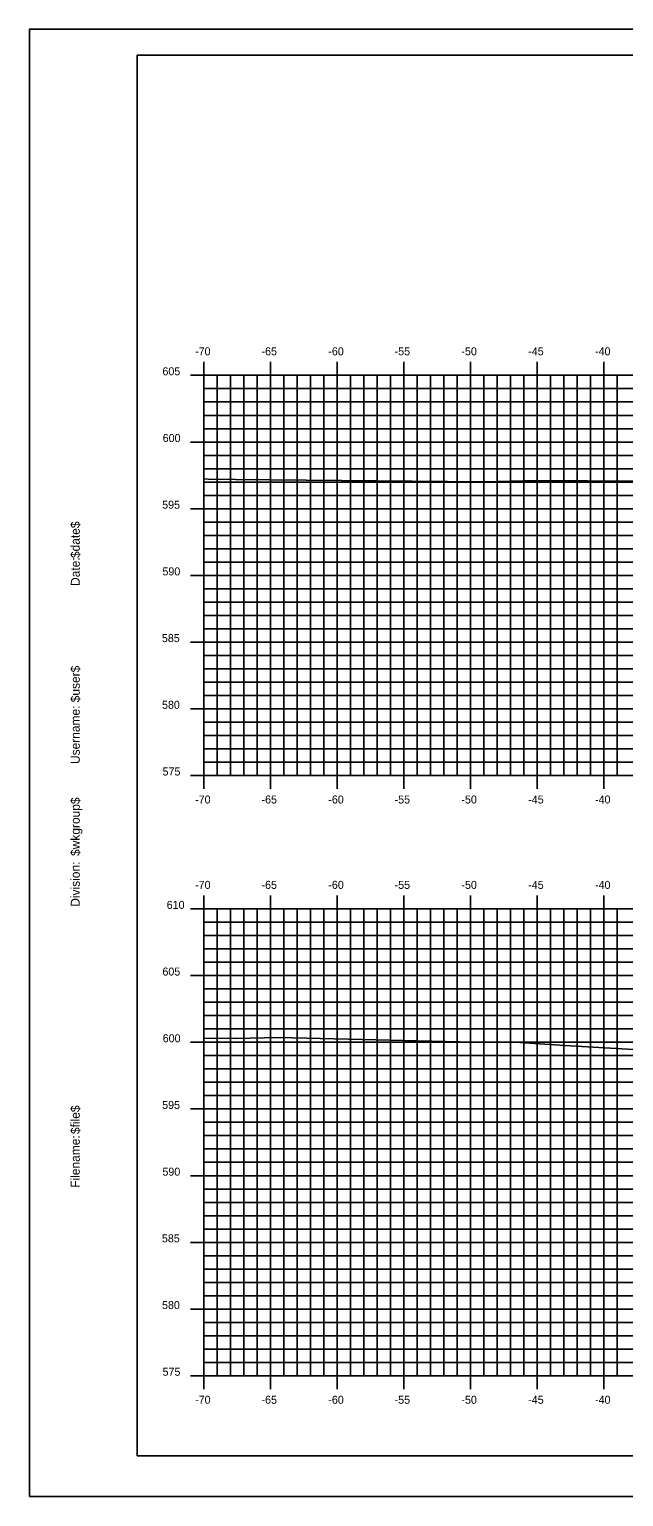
# Model space of a CAD drawing. Extents: x 1073864 to 1074034, y 779716 to 779826.
# Drawn here: x 1073864.4 to 1073908.9, y 779715.6 to 779825.6 of the extents above; entities that cross this region are included whole.
import ezdxf

# ---------------------------------------------------------------- set-up
doc = ezdxf.new("R2010")
doc.units = 0
for name, color, linetype in [('BORDER', 7, 'Continuous'), ('H_V ANNOTATION', 7, 'Continuous'), ('MAJOR', 7, 'Continuous'), ('MINOR', 7, 'Continuous'), ('PLOT BOUNDARY', 7, 'Continuous'), ('S_Roadway_Centerline', 7, 'Continuous')]:
    doc.layers.add(name, color=color, linetype=linetype)

msp = doc.modelspace()

# ---------------------------------------------------------------- linework, layer by layer
at = {"layer": 'BORDER'}
msp.add_lwpolyline([(1073872.47, 779718.71), (1074032.47, 779718.71), (1074032.47, 779823.71), (1073872.47, 779823.71)], close=True, dxfattribs=at)
at = {"layer": 'MAJOR'}
for p, q in [((1073877.47, 779800.71), (1073877.47, 779799.71)), ((1073882.47, 779800.71), (1073882.47, 779799.71)), ((1073887.47, 779800.71), (1073887.47, 779799.71)), ((1073892.47, 779800.71), (1073892.47, 779799.71)), ((1073897.47, 779800.71), (1073897.47, 779799.71)), ((1073902.47, 779800.71), (1073902.47, 779799.71)), ((1073907.47, 779800.71), (1073907.47, 779799.71)), ((1073876.47, 779799.71), (1073877.47, 779799.71)), ((1073877.47, 779799.71), (1074017.47, 779799.71)), ((1073877.47, 779769.71), (1073877.47, 779799.71)), ((1073877.47, 779769.71), (1073877.47, 779799.71)), ((1073877.47, 779799.71), (1074017.47, 779799.71)), ((1073882.47, 779769.71), (1073882.47, 779799.71)), ((1073887.47, 779769.71), (1073887.47, 779799.71)), ((1073892.47, 779769.71), (1073892.47, 779799.71)), ((1073897.47, 779769.71), (1073897.47, 779799.71)), ((1073902.47, 779769.71), (1073902.47, 779799.71)), ((1073907.47, 779769.71), (1073907.47, 779799.71)), ((1073876.47, 779794.71), (1073877.47, 779794.71)), ((1073877.47, 779794.71), (1074017.47, 779794.71)), ((1073876.47, 779789.71), (1073877.47, 779789.71)), ((1073877.47, 779789.71), (1074017.47, 779789.71)), ((1073876.47, 779784.71), (1073877.47, 779784.71)), ((1073877.47, 779784.71), (1074017.47, 779784.71)), ((1073876.47, 779779.71), (1073877.47, 779779.71)), ((1073877.47, 779779.71), (1074017.47, 779779.71)), ((1073876.47, 779774.71), (1073877.47, 779774.71)), ((1073877.47, 779774.71), (1074017.47, 779774.71)), ((1073876.47, 779769.71), (1073877.47, 779769.71)), ((1073877.47, 779769.71), (1074017.47, 779769.71)), ((1073877.47, 779769.71), (1074017.47, 779769.71)), ((1073877.47, 779768.7), (1073877.47, 779769.71)), ((1073882.47, 779768.7), (1073882.47, 779769.71)), ((1073887.47, 779768.7), (1073887.47, 779769.71)), ((1073892.47, 779768.7), (1073892.47, 779769.71)), ((1073897.47, 779768.7), (1073897.47, 779769.71)), ((1073902.47, 779768.7), (1073902.47, 779769.71)), ((1073907.47, 779768.7), (1073907.47, 779769.71)), ((1073877.47, 779760.71), (1073877.47, 779759.71)), ((1073882.47, 779760.71), (1073882.47, 779759.71)), ((1073887.47, 779760.71), (1073887.47, 779759.71)), ((1073892.47, 779760.71), (1073892.47, 779759.71)), ((1073897.47, 779760.71), (1073897.47, 779759.71)), ((1073902.47, 779760.71), (1073902.47, 779759.71)), ((1073907.47, 779760.71), (1073907.47, 779759.71)), ((1073876.47, 779759.71), (1073877.47, 779759.71)), ((1073877.47, 779759.71), (1074017.47, 779759.71)), ((1073877.47, 779724.71), (1073877.47, 779759.71)), ((1073877.47, 779724.71), (1073877.47, 779759.71)), ((1073877.47, 779759.71), (1074017.47, 779759.71)), ((1073882.47, 779724.71), (1073882.47, 779759.71)), ((1073887.47, 779724.71), (1073887.47, 779759.71)), ((1073892.47, 779724.71), (1073892.47, 779759.71)), ((1073897.47, 779724.71), (1073897.47, 779759.71)), ((1073902.47, 779724.71), (1073902.47, 779759.71)), ((1073907.47, 779724.71), (1073907.47, 779759.71)), ((1073876.47, 779754.71), (1073877.47, 779754.71)), ((1073877.47, 779754.71), (1074017.47, 779754.71)), ((1073876.47, 779749.71), (1073877.47, 779749.71)), ((1073877.47, 779749.71), (1074017.47, 779749.71)), ((1073876.47, 779744.71), (1073877.47, 779744.71)), ((1073877.47, 779744.71), (1074017.47, 779744.71)), ((1073876.47, 779739.71), (1073877.47, 779739.71)), ((1073877.47, 779739.71), (1074017.47, 779739.71)), ((1073876.47, 779734.71), (1073877.47, 779734.71)), ((1073877.47, 779734.71), (1074017.47, 779734.71)), ((1073876.47, 779729.71), (1073877.47, 779729.71)), ((1073877.47, 779729.71), (1074017.47, 779729.71)), ((1073876.47, 779724.71), (1073877.47, 779724.71)), ((1073877.47, 779724.71), (1074017.47, 779724.71)), ((1073877.47, 779724.71), (1074017.47, 779724.71)), ((1073877.47, 779723.7), (1073877.47, 779724.71)), ((1073882.47, 779723.7), (1073882.47, 779724.71)), ((1073887.47, 779723.7), (1073887.47, 779724.71)), ((1073892.47, 779723.7), (1073892.47, 779724.71)), ((1073897.47, 779723.7), (1073897.47, 779724.71)), ((1073902.47, 779723.7), (1073902.47, 779724.71)), ((1073907.47, 779723.7), (1073907.47, 779724.71))]:
    msp.add_line(p, q, dxfattribs=at)
at = {"layer": 'MINOR'}
for p, q in [((1073878.47, 779769.71), (1073878.47, 779799.71)), ((1073879.47, 779769.71), (1073879.47, 779799.71)), ((1073880.47, 779769.71), (1073880.47, 779799.71)), ((1073881.47, 779769.71), (1073881.47, 779799.71)), ((1073883.47, 779769.71), (1073883.47, 779799.71)), ((1073884.47, 779769.71), (1073884.47, 779799.71)), ((1073885.47, 779769.71), (1073885.47, 779799.71)), ((1073886.47, 779769.71), (1073886.47, 779799.71)), ((1073888.47, 779769.71), (1073888.47, 779799.71)), ((1073889.47, 779769.71), (1073889.47, 779799.71)), ((1073890.47, 779769.71), (1073890.47, 779799.71)), ((1073891.47, 779769.71), (1073891.47, 779799.71)), ((1073893.47, 779769.71), (1073893.47, 779799.71)), ((1073894.47, 779769.71), (1073894.47, 779799.71)), ((1073895.47, 779769.71), (1073895.47, 779799.71)), ((1073896.47, 779769.71), (1073896.47, 779799.71)), ((1073898.47, 779769.71), (1073898.47, 779799.71)), ((1073899.47, 779769.71), (1073899.47, 779799.71)), ((1073900.47, 779769.71), (1073900.47, 779799.71)), ((1073901.47, 779769.71), (1073901.47, 779799.71)), ((1073903.47, 779769.71), (1073903.47, 779799.71)), ((1073904.47, 779769.71), (1073904.47, 779799.71)), ((1073905.47, 779769.71), (1073905.47, 779799.71)), ((1073906.47, 779769.71), (1073906.47, 779799.71)), ((1073908.47, 779769.71), (1073908.47, 779799.71)), ((1073877.47, 779798.71), (1074017.47, 779798.71)), ((1073877.47, 779798.71), (1073878.47, 779798.71)), ((1073877.47, 779797.71), (1074017.47, 779797.71)), ((1073877.47, 779797.71), (1073878.47, 779797.71)), ((1073877.47, 779796.71), (1074017.47, 779796.71)), ((1073877.47, 779796.71), (1073878.47, 779796.71)), ((1073877.47, 779795.71), (1074017.47, 779795.71)), ((1073877.47, 779795.71), (1073878.47, 779795.71)), ((1073877.47, 779793.71), (1074017.47, 779793.71)), ((1073877.47, 779793.71), (1073878.47, 779793.71)), ((1073877.47, 779792.71), (1074017.47, 779792.71)), ((1073877.47, 779792.71), (1073878.47, 779792.71)), ((1073877.47, 779791.71), (1074017.47, 779791.71)), ((1073877.47, 779791.71), (1073878.47, 779791.71)), ((1073877.47, 779790.71), (1074017.47, 779790.71)), ((1073877.47, 779790.71), (1073878.47, 779790.71)), ((1073877.47, 779788.71), (1074017.47, 779788.71)), ((1073877.47, 779788.71), (1073878.47, 779788.71)), ((1073877.47, 779787.71), (1074017.47, 779787.71)), ((1073877.47, 779787.71), (1073878.47, 779787.71)), ((1073877.47, 779786.71), (1074017.47, 779786.71)), ((1073877.47, 779786.71), (1073878.47, 779786.71)), ((1073877.47, 779785.71), (1074017.47, 779785.71)), ((1073877.47, 779785.71), (1073878.47, 779785.71)), ((1073877.47, 779783.71), (1074017.47, 779783.71)), ((1073877.47, 779783.71), (1073878.47, 779783.71)), ((1073877.47, 779782.71), (1074017.47, 779782.71)), ((1073877.47, 779782.71), (1073878.47, 779782.71)), ((1073877.47, 779781.71), (1074017.47, 779781.71)), ((1073877.47, 779781.71), (1073878.47, 779781.71)), ((1073877.47, 779780.71), (1074017.47, 779780.71)), ((1073877.47, 779780.71), (1073878.47, 779780.71)), ((1073877.47, 779778.71), (1074017.47, 779778.71)), ((1073877.47, 779778.71), (1073878.47, 779778.71)), ((1073877.47, 779777.71), (1074017.47, 779777.71)), ((1073877.47, 779777.71), (1073878.47, 779777.71)), ((1073877.47, 779776.71), (1074017.47, 779776.71)), ((1073877.47, 779776.71), (1073878.47, 779776.71)), ((1073877.47, 779775.71), (1074017.47, 779775.71)), ((1073877.47, 779775.71), (1073878.47, 779775.71)), ((1073877.47, 779773.71), (1074017.47, 779773.71)), ((1073877.47, 779773.71), (1073878.47, 779773.71)), ((1073877.47, 779772.71), (1074017.47, 779772.71)), ((1073877.47, 779772.71), (1073878.47, 779772.71)), ((1073877.47, 779771.71), (1074017.47, 779771.71)), ((1073877.47, 779771.71), (1073878.47, 779771.71)), ((1073877.47, 779770.71), (1074017.47, 779770.71)), ((1073877.47, 779770.71), (1073878.47, 779770.71)), ((1073878.47, 779724.71), (1073878.47, 779759.71)), ((1073879.47, 779724.71), (1073879.47, 779759.71)), ((1073880.47, 779724.71), (1073880.47, 779759.71)), ((1073881.47, 779724.71), (1073881.47, 779759.71)), ((1073883.47, 779724.71), (1073883.47, 779759.71)), ((1073884.47, 779724.71), (1073884.47, 779759.71)), ((1073885.47, 779724.71), (1073885.47, 779759.71)), ((1073886.47, 779724.71), (1073886.47, 779759.71)), ((1073888.47, 779724.71), (1073888.47, 779759.71)), ((1073889.47, 779724.71), (1073889.47, 779759.71)), ((1073890.47, 779724.71), (1073890.47, 779759.71)), ((1073891.47, 779724.71), (1073891.47, 779759.71)), ((1073893.47, 779724.71), (1073893.47, 779759.71)), ((1073894.47, 779724.71), (1073894.47, 779759.71)), ((1073895.47, 779724.71), (1073895.47, 779759.71)), ((1073896.47, 779724.71), (1073896.47, 779759.71)), ((1073898.47, 779724.71), (1073898.47, 779759.71)), ((1073899.47, 779724.71), (1073899.47, 779759.71)), ((1073900.47, 779724.71), (1073900.47, 779759.71)), ((1073901.47, 779724.71), (1073901.47, 779759.71)), ((1073903.47, 779724.71), (1073903.47, 779759.71)), ((1073904.47, 779724.71), (1073904.47, 779759.71)), ((1073905.47, 779724.71), (1073905.47, 779759.71)), ((1073906.47, 779724.71), (1073906.47, 779759.71)), ((1073908.47, 779724.71), (1073908.47, 779759.71)), ((1073877.47, 779758.71), (1074017.47, 779758.71)), ((1073877.47, 779758.71), (1073878.47, 779758.71)), ((1073877.47, 779757.71), (1074017.47, 779757.71)), ((1073877.47, 779757.71), (1073878.47, 779757.71)), ((1073877.47, 779756.71), (1074017.47, 779756.71)), ((1073877.47, 779756.71), (1073878.47, 779756.71)), ((1073877.47, 779755.71), (1074017.47, 779755.71)), ((1073877.47, 779755.71), (1073878.47, 779755.71)), ((1073877.47, 779753.71), (1074017.47, 779753.71)), ((1073877.47, 779753.71), (1073878.47, 779753.71)), ((1073877.47, 779752.71), (1074017.47, 779752.71)), ((1073877.47, 779752.71), (1073878.47, 779752.71)), ((1073877.47, 779751.71), (1074017.47, 779751.71)), ((1073877.47, 779751.71), (1073878.47, 779751.71)), ((1073877.47, 779750.71), (1074017.47, 779750.71)), ((1073877.47, 779750.71), (1073878.47, 779750.71)), ((1073877.47, 779748.71), (1074017.47, 779748.71)), ((1073877.47, 779748.71), (1073878.47, 779748.71)), ((1073877.47, 779747.71), (1074017.47, 779747.71)), ((1073877.47, 779747.71), (1073878.47, 779747.71)), ((1073877.47, 779746.71), (1074017.47, 779746.71)), ((1073877.47, 779746.71), (1073878.47, 779746.71)), ((1073877.47, 779745.71), (1074017.47, 779745.71)), ((1073877.47, 779745.71), (1073878.47, 779745.71)), ((1073877.47, 779743.71), (1074017.47, 779743.71)), ((1073877.47, 779743.71), (1073878.47, 779743.71)), ((1073877.47, 779742.71), (1074017.47, 779742.71)), ((1073877.47, 779742.71), (1073878.47, 779742.71)), ((1073877.47, 779741.71), (1074017.47, 779741.71)), ((1073877.47, 779741.71), (1073878.47, 779741.71)), ((1073877.47, 779740.71), (1074017.47, 779740.71)), ((1073877.47, 779740.71), (1073878.47, 779740.71)), ((1073877.47, 779738.71), (1074017.47, 779738.71)), ((1073877.47, 779738.71), (1073878.47, 779738.71)), ((1073877.47, 779737.71), (1074017.47, 779737.71)), ((1073877.47, 779737.71), (1073878.47, 779737.71)), ((1073877.47, 779736.71), (1074017.47, 779736.71)), ((1073877.47, 779736.71), (1073878.47, 779736.71)), ((1073877.47, 779735.71), (1074017.47, 779735.71)), ((1073877.47, 779735.71), (1073878.47, 779735.71)), ((1073877.47, 779733.71), (1074017.47, 779733.71)), ((1073877.47, 779733.71), (1073878.47, 779733.71)), ((1073877.47, 779732.71), (1074017.47, 779732.71)), ((1073877.47, 779732.71), (1073878.47, 779732.71)), ((1073877.47, 779731.71), (1074017.47, 779731.71)), ((1073877.47, 779731.71), (1073878.47, 779731.71)), ((1073877.47, 779730.71), (1074017.47, 779730.71)), ((1073877.47, 779730.71), (1073878.47, 779730.71)), ((1073877.47, 779728.71), (1074017.47, 779728.71)), ((1073877.47, 779728.71), (1073878.47, 779728.71)), ((1073877.47, 779727.71), (1074017.47, 779727.71)), ((1073877.47, 779727.71), (1073878.47, 779727.71)), ((1073877.47, 779726.71), (1074017.47, 779726.71)), ((1073877.47, 779726.71), (1073878.47, 779726.71)), ((1073877.47, 779725.71), (1074017.47, 779725.71)), ((1073877.47, 779725.71), (1073878.47, 779725.71))]:
    msp.add_line(p, q, dxfattribs=at)
at = {"layer": 'PLOT BOUNDARY'}
msp.add_lwpolyline([(1073864.38, 779715.65), (1074034.38, 779715.65), (1074034.38, 779825.65), (1073864.38, 779825.65)], close=True, dxfattribs=at)
at = {"layer": 'S_Roadway_Centerline'}
for points in [[(1073877.47, 779791.94), (1073877.8, 779791.93), (1073879.84, 779791.91), (1073898.39, 779791.73), (1073902.54, 779791.83), (1073909.97, 779791.77)], [(1073877.47, 779750.02), (1073879.9, 779749.99), (1073883.07, 779750.08), (1073897.68, 779749.72), (1073901.15, 779749.7), (1073904.53, 779749.47), (1073914.79, 779748.86)]]:
    msp.add_lwpolyline(points, dxfattribs=at)

# ---------------------------------------------------------------- texts
at = {"layer": 'BORDER'}
for s, p in [('$date$', (1073868.16, 779786.01)), ('Date:', (1073868.16, 779783.92)), ('$user$', (1073868.16, 779775.2)), ('Username:', (1073868.16, 779770.57)), ('$wkgroup$', (1073868.16, 779763.68)), ('Division:', (1073868.16, 779759.87)), ('$file$', (1073868.16, 779742.83)), ('Filename:', (1073868.16, 779738.8))]:
    msp.add_text(s, height=0.67, rotation=90, dxfattribs=at).set_placement(p)
at = {"layer": 'H_V ANNOTATION'}
for s, p in [('-70', (1073876.81, 779801.21)), ('-65', (1073881.79, 779801.21)), ('-60', (1073886.8, 779801.21)), ('-55', (1073891.77, 779801.21)), ('-50', (1073896.78, 779801.21)), ('-45', (1073901.79, 779801.21)), ('-40', (1073906.8, 779801.21)), ('605', (1073874.36, 779799.71)), ('600', (1073874.38, 779794.71)), ('595', (1073874.34, 779789.71)), ('590', (1073874.36, 779784.71)), ('585', (1073874.32, 779779.71)), ('580', (1073874.33, 779774.71)), ('575', (1073874.37, 779769.71)), ('-70', (1073876.81, 779767.61)), ('-65', (1073881.79, 779767.61)), ('-60', (1073886.8, 779767.61)), ('-55', (1073891.77, 779767.61)), ('-50', (1073896.78, 779767.61)), ('-45', (1073901.79, 779767.61)), ('-40', (1073906.8, 779767.61)), ('-70', (1073876.81, 779761.21)), ('-65', (1073881.79, 779761.21)), ('-60', (1073886.8, 779761.21)), ('-55', (1073891.77, 779761.21)), ('-50', (1073896.78, 779761.21)), ('-45', (1073901.79, 779761.21)), ('-40', (1073906.8, 779761.21)), ('610', (1073874.68, 779759.71)), ('605', (1073874.36, 779754.71)), ('600', (1073874.38, 779749.71)), ('595', (1073874.34, 779744.71)), ('590', (1073874.36, 779739.71)), ('585', (1073874.32, 779734.71)), ('580', (1073874.33, 779729.71)), ('575', (1073874.37, 779724.71)), ('-70', (1073876.81, 779722.61)), ('-65', (1073881.79, 779722.61)), ('-60', (1073886.8, 779722.61)), ('-55', (1073891.77, 779722.61)), ('-50', (1073896.78, 779722.61)), ('-45', (1073901.79, 779722.61)), ('-40', (1073906.8, 779722.61))]:
    msp.add_text(s, height=0.6, dxfattribs=at).set_placement(p)
at = {"layer": 'MAJOR'}
for p in [(1073877.47, 779769.71), (1073877.47, 779724.71)]:
    msp.add_text('-', height=0.006, dxfattribs=at).set_placement(p)

doc.saveas('drawing.dxf')
